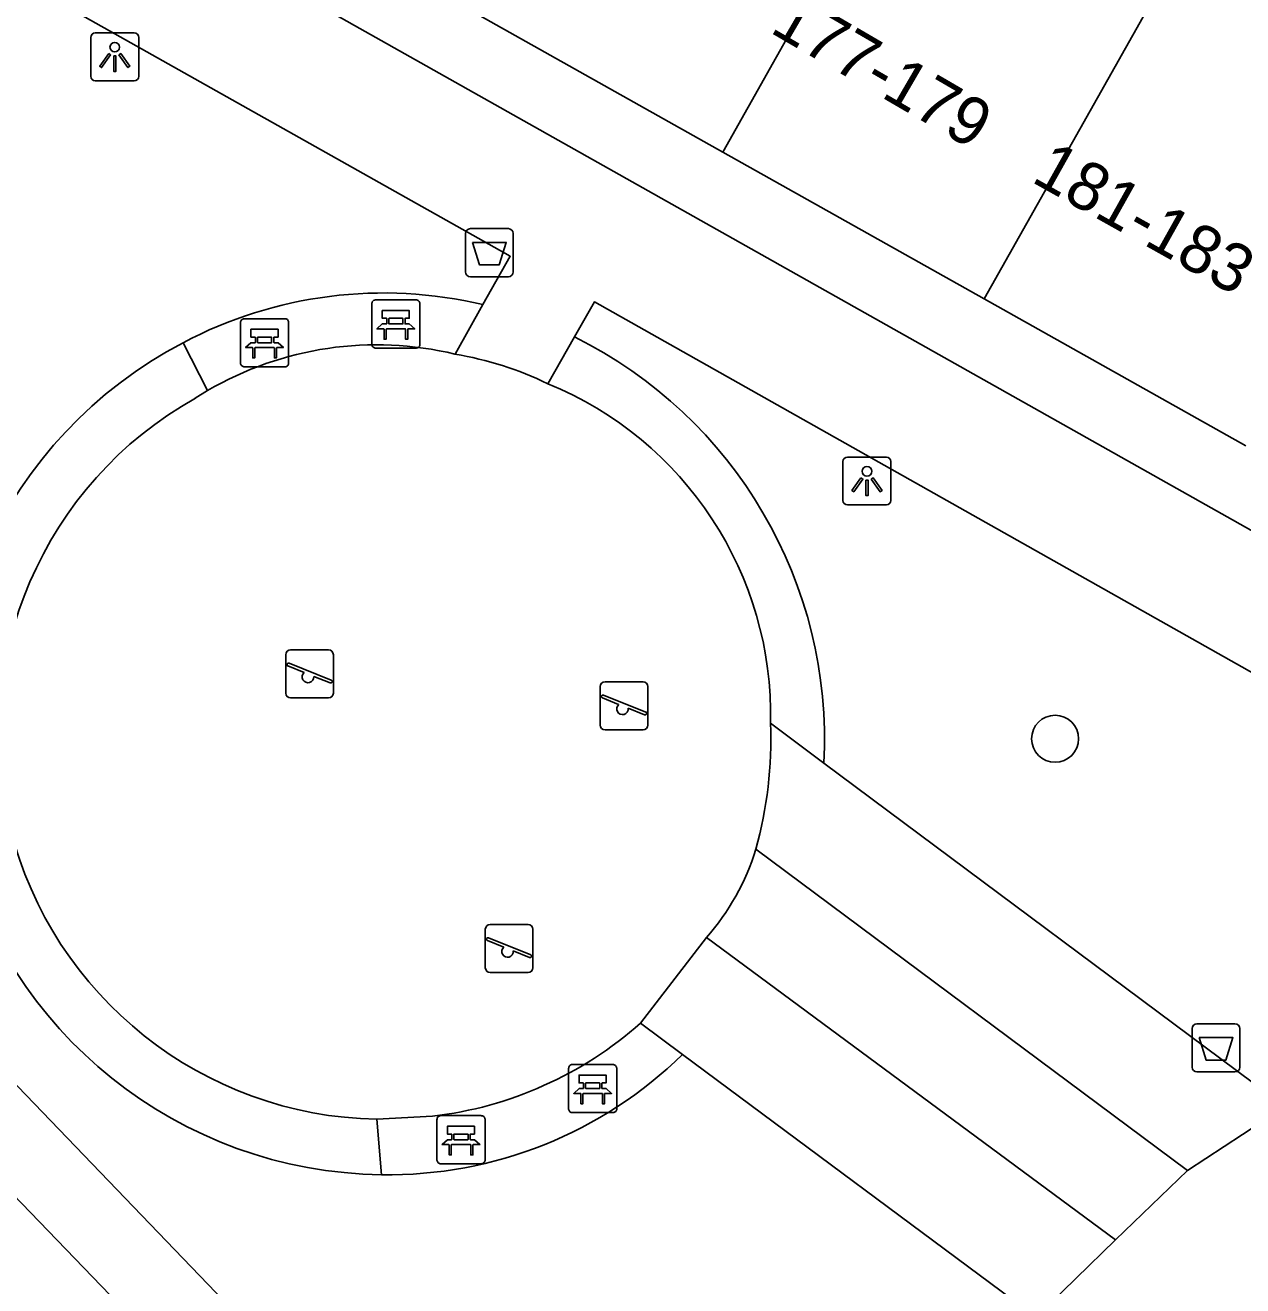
# Model space of a CAD drawing. Extents: x 159280 to 160375, y 384531 to 385872.
# Drawn here: x 159682.94 to 159708.26, y 384897.02 to 384923.23 of the extents above; entities that cross this region are included whole.
import ezdxf

# ---------------------------------------------------------------- set-up
doc = ezdxf.new("R2010")
doc.units = 0
for name, color, linetype in [('IMGEO_Afvalbak', 7, 'Continuous'), ('IMGEO_Bank', 7, 'Continuous'), ('IMGEO_Boom', 7, 'Continuous'), ('IMGEO_Groenvoorziening', 7, 'Continuous'), ('IMGEO_Haag', 7, 'Continuous'), ('IMGEO_Lichtpunt', 7, 'Continuous'), ('IMGEO_Pand', 7, 'Continuous'), ('IMGEO_Pand_nummerreeks', 7, 'Continuous'), ('IMGEO_Speelvoorziening', 7, 'Continuous'), ('IMGEO_Voetpad_open', 7, 'Continuous')]:
    doc.layers.add(name, color=color, linetype=linetype)

msp = doc.modelspace()

# ---------------------------------------------------------------- linework, layer by layer
at = {"layer": 'IMGEO_Afvalbak'}
for p, q in [((159692.098, 384918.1), (159692.098, 384918.9)), ((159692.098, 384918.9), (159692.098, 384918.1)), ((159692.198, 384919), (159692.988, 384919)), ((159692.988, 384919), (159692.198, 384919)), ((159693.088, 384918.9), (159693.088, 384918.1)), ((159693.088, 384918.1), (159693.088, 384918.9)), ((159692.988, 384918), (159692.198, 384918)), ((159692.198, 384918), (159692.988, 384918)), ((159707.207, 384901.565), (159707.207, 384902.365)), ((159707.207, 384902.365), (159707.207, 384901.565)), ((159707.307, 384902.465), (159708.097, 384902.465)), ((159708.097, 384902.465), (159707.307, 384902.465)), ((159708.197, 384902.365), (159708.197, 384901.565)), ((159708.197, 384901.565), (159708.197, 384902.365)), ((159708.097, 384901.465), (159707.307, 384901.465)), ((159707.307, 384901.465), (159708.097, 384901.465))]:
    msp.add_line(p, q, dxfattribs=at)
for points in [[(159692.241, 384918.714), (159692.945, 384918.714), (159692.796, 384918.244), (159692.39, 384918.244), (159692.241, 384918.714)], [(159707.35, 384902.179), (159708.054, 384902.179), (159707.905, 384901.709), (159707.499, 384901.709), (159707.35, 384902.179)]]:
    msp.add_lwpolyline(points, dxfattribs=at)
for centre, start, end in [((159692.198, 384918.9), 90, 180), ((159692.198, 384918.9), 90, 180), ((159692.988, 384918.9), 0, 90), ((159692.988, 384918.9), 360, 90), ((159692.198, 384918.1), 180, 270), ((159692.198, 384918.1), 180, 270), ((159692.988, 384918.1), 270, 0), ((159692.988, 384918.1), 270, 0), ((159707.307, 384902.365), 90, 180), ((159707.307, 384902.365), 90, 180), ((159708.097, 384902.365), 0, 90), ((159708.097, 384902.365), 360, 90), ((159707.307, 384901.565), 180, 270), ((159707.307, 384901.565), 180, 270), ((159708.097, 384901.565), 270, 0), ((159708.097, 384901.565), 270, 0)]:
    msp.add_arc(centre, 0.1, start, end, dxfattribs=at)
at = {"layer": 'IMGEO_Bank'}
for p, q in [((159690.223, 384917.517), (159691.064, 384917.517)), ((159691.064, 384917.517), (159690.223, 384917.517)), ((159690.148, 384916.592), (159690.148, 384917.433)), ((159690.148, 384917.433), (159690.148, 384916.592)), ((159691.148, 384917.442), (159691.148, 384916.601)), ((159691.148, 384916.601), (159691.148, 384917.442)), ((159687.418, 384916.202), (159687.418, 384917.043)), ((159687.418, 384917.043), (159687.418, 384916.202)), ((159687.493, 384917.127), (159688.334, 384917.127)), ((159688.334, 384917.127), (159687.493, 384917.127)), ((159688.418, 384917.052), (159688.418, 384916.211)), ((159688.418, 384916.211), (159688.418, 384917.052)), ((159690.457, 384917.023), (159690.457, 384917.129)), ((159690.501, 384917.129), (159690.501, 384917.023)), ((159690.789, 384917.135), (159690.507, 384917.135)), ((159690.507, 384917.017), (159690.789, 384917.017)), ((159690.795, 384917.023), (159690.795, 384917.129)), ((159690.839, 384917.129), (159690.839, 384917.023)), ((159687.727, 384916.633), (159687.727, 384916.739)), ((159687.771, 384916.739), (159687.771, 384916.633)), ((159688.059, 384916.745), (159687.777, 384916.745)), ((159688.065, 384916.633), (159688.065, 384916.739)), ((159688.109, 384916.739), (159688.109, 384916.633)), ((159690.845, 384916.915), (159690.452, 384916.915)), ((159688.115, 384916.525), (159687.722, 384916.525)), ((159687.777, 384916.627), (159688.059, 384916.627)), ((159691.073, 384916.517), (159690.232, 384916.517)), ((159690.232, 384916.517), (159691.073, 384916.517)), ((159688.343, 384916.127), (159687.502, 384916.127)), ((159687.502, 384916.127), (159688.343, 384916.127)), ((159694.241, 384900.694), (159694.241, 384901.535)), ((159694.241, 384901.535), (159694.241, 384900.694)), ((159694.316, 384901.619), (159695.157, 384901.619)), ((159695.157, 384901.619), (159694.316, 384901.619)), ((159695.241, 384901.544), (159695.241, 384900.703)), ((159695.241, 384900.703), (159695.241, 384901.544)), ((159694.882, 384901.237), (159694.6, 384901.237)), ((159694.938, 384901.017), (159694.545, 384901.017)), ((159694.55, 384901.125), (159694.55, 384901.231)), ((159694.594, 384901.231), (159694.594, 384901.125)), ((159694.6, 384901.119), (159694.882, 384901.119)), ((159694.888, 384901.125), (159694.888, 384901.231)), ((159694.932, 384901.231), (159694.932, 384901.125)), ((159691.503, 384899.631), (159691.503, 384900.472)), ((159691.503, 384900.472), (159691.503, 384899.631)), ((159691.578, 384900.556), (159692.419, 384900.556)), ((159692.419, 384900.556), (159691.578, 384900.556)), ((159692.503, 384900.481), (159692.503, 384899.64)), ((159692.503, 384899.64), (159692.503, 384900.481)), ((159695.166, 384900.619), (159694.325, 384900.619)), ((159694.325, 384900.619), (159695.166, 384900.619)), ((159692.2, 384899.954), (159691.807, 384899.954)), ((159691.812, 384900.062), (159691.812, 384900.168)), ((159691.856, 384900.168), (159691.856, 384900.062)), ((159692.144, 384900.174), (159691.862, 384900.174)), ((159691.862, 384900.056), (159692.144, 384900.056)), ((159692.15, 384900.062), (159692.15, 384900.168)), ((159692.194, 384900.168), (159692.194, 384900.062)), ((159692.428, 384899.556), (159691.587, 384899.556)), ((159691.587, 384899.556), (159692.428, 384899.556))]:
    msp.add_line(p, q, dxfattribs=at)
for points in [[(159690.451, 384917.135), (159690.365, 384917.135), (159690.365, 384917.296), (159690.928, 384917.296), (159690.928, 384917.135), (159690.845, 384917.135)], [(159690.395, 384916.915), (159690.253, 384916.915), (159690.365, 384917.017), (159690.451, 384917.017)], [(159690.845, 384917.017), (159690.928, 384917.017), (159691.04, 384916.915), (159690.901, 384916.915)], [(159687.721, 384916.745), (159687.635, 384916.745), (159687.635, 384916.906), (159688.198, 384916.906), (159688.198, 384916.745), (159688.115, 384916.745)], [(159690.445, 384916.908), (159690.445, 384916.701), (159690.402, 384916.701), (159690.402, 384916.908)], [(159690.895, 384916.908), (159690.895, 384916.701), (159690.851, 384916.701), (159690.851, 384916.908)], [(159687.665, 384916.525), (159687.523, 384916.525), (159687.635, 384916.627), (159687.721, 384916.627)], [(159687.715, 384916.518), (159687.715, 384916.311), (159687.672, 384916.311), (159687.672, 384916.518)], [(159688.115, 384916.627), (159688.198, 384916.627), (159688.31, 384916.525), (159688.171, 384916.525)], [(159688.165, 384916.518), (159688.165, 384916.311), (159688.121, 384916.311), (159688.121, 384916.518)], [(159694.544, 384901.237), (159694.458, 384901.237), (159694.458, 384901.398), (159695.021, 384901.398), (159695.021, 384901.237), (159694.938, 384901.237)], [(159694.488, 384901.017), (159694.346, 384901.017), (159694.458, 384901.119), (159694.544, 384901.119)], [(159694.538, 384901.01), (159694.538, 384900.803), (159694.495, 384900.803), (159694.495, 384901.01)], [(159694.938, 384901.119), (159695.021, 384901.119), (159695.133, 384901.017), (159694.994, 384901.017)], [(159694.988, 384901.01), (159694.988, 384900.803), (159694.944, 384900.803), (159694.944, 384901.01)], [(159691.806, 384900.174), (159691.72, 384900.174), (159691.72, 384900.335), (159692.283, 384900.335), (159692.283, 384900.174), (159692.2, 384900.174)], [(159691.75, 384899.954), (159691.608, 384899.954), (159691.72, 384900.056), (159691.806, 384900.056)], [(159691.8, 384899.947), (159691.8, 384899.74), (159691.757, 384899.74), (159691.757, 384899.947)], [(159692.2, 384900.056), (159692.283, 384900.056), (159692.395, 384899.954), (159692.256, 384899.954)], [(159692.25, 384899.947), (159692.25, 384899.74), (159692.206, 384899.74), (159692.206, 384899.947)]]:
    msp.add_lwpolyline(points, dxfattribs=at)
for centre, radius, start, end in [((159690.226, 384917.439), 0.0779, 92.4484, 184.2845), ((159690.226, 384917.439), 0.0779, 92.4484, 184.2845), ((159691.07, 384917.439), 0.0779, 2.4484, 94.2845), ((159691.07, 384917.439), 0.0779, 2.4484, 94.2845), ((159687.496, 384917.049), 0.0779, 92.4484, 184.2845), ((159687.496, 384917.049), 0.0779, 92.4484, 184.2845), ((159688.34, 384917.049), 0.0779, 2.4484, 94.2845), ((159688.34, 384917.049), 0.0779, 2.4484, 94.2845), ((159690.45, 384917.128), 0.00671, 2.8957, 87.1043), ((159690.45, 384917.024), 0.00671, 272.8957, 357.1043), ((159690.507, 384917.128), 0.00671, 92.8957, 177.1043), ((159690.507, 384917.024), 0.00671, 182.8957, 267.1043), ((159690.789, 384917.128), 0.00671, 2.8957, 87.1043), ((159690.789, 384917.024), 0.00671, 272.8957, 357.1043), ((159690.846, 384917.128), 0.00671, 92.8957, 177.1043), ((159690.846, 384917.024), 0.00671, 182.8957, 267.1043), ((159687.72, 384916.738), 0.00671, 2.8957, 87.1043), ((159687.777, 384916.738), 0.00671, 92.8957, 177.1043), ((159688.059, 384916.738), 0.00671, 2.8957, 87.1043), ((159688.116, 384916.738), 0.00671, 92.8957, 177.1043), ((159690.395, 384916.908), 0.00671, 2.8957, 87.1043), ((159690.452, 384916.908), 0.00671, 92.8957, 177.1043), ((159690.844, 384916.908), 0.00671, 2.8957, 87.1043), ((159690.901, 384916.908), 0.00671, 92.8957, 177.1043), ((159687.665, 384916.518), 0.00671, 2.8957, 87.1043), ((159687.722, 384916.518), 0.00671, 92.8957, 177.1043), ((159687.72, 384916.634), 0.00671, 272.8957, 357.1043), ((159687.777, 384916.634), 0.00671, 182.8957, 267.1043), ((159688.059, 384916.634), 0.00671, 272.8957, 357.1043), ((159688.116, 384916.634), 0.00671, 182.8957, 267.1043), ((159688.114, 384916.518), 0.00671, 2.8957, 87.1043), ((159688.171, 384916.518), 0.00671, 92.8957, 177.1043), ((159690.226, 384916.595), 0.0779, 182.4484, 274.2845), ((159690.226, 384916.595), 0.0779, 182.4484, 274.2845), ((159691.07, 384916.595), 0.0779, 272.4484, 4.2845), ((159691.07, 384916.595), 0.0779, 272.4484, 4.2845), ((159687.496, 384916.205), 0.0779, 182.4484, 274.2845), ((159687.496, 384916.205), 0.0779, 182.4484, 274.2845), ((159688.34, 384916.205), 0.0779, 272.4484, 4.2845), ((159688.34, 384916.205), 0.0779, 272.4484, 4.2845), ((159694.319, 384901.541), 0.0779, 92.4484, 184.2845), ((159694.319, 384901.541), 0.0779, 92.4484, 184.2845), ((159695.163, 384901.541), 0.0779, 2.4484, 94.2845), ((159695.163, 384901.541), 0.0779, 2.4484, 94.2845), ((159694.543, 384901.23), 0.00671, 2.8957, 87.1043), ((159694.6, 384901.23), 0.00671, 92.8957, 177.1043), ((159694.882, 384901.23), 0.00671, 2.8957, 87.1043), ((159694.939, 384901.23), 0.00671, 92.8957, 177.1043), ((159694.488, 384901.01), 0.00671, 2.8957, 87.1043), ((159694.545, 384901.01), 0.00671, 92.8957, 177.1043), ((159694.543, 384901.126), 0.00671, 272.8957, 357.1043), ((159694.6, 384901.126), 0.00671, 182.8957, 267.1043), ((159694.882, 384901.126), 0.00671, 272.8957, 357.1043), ((159694.939, 384901.126), 0.00671, 182.8957, 267.1043), ((159694.937, 384901.01), 0.00671, 2.8957, 87.1043), ((159694.994, 384901.01), 0.00671, 92.8957, 177.1043), ((159691.581, 384900.478), 0.0779, 92.4484, 184.2845), ((159691.581, 384900.478), 0.0779, 92.4484, 184.2845), ((159692.425, 384900.478), 0.0779, 2.4484, 94.2845), ((159692.425, 384900.478), 0.0779, 2.4484, 94.2845), ((159694.319, 384900.697), 0.0779, 182.4484, 274.2845), ((159694.319, 384900.697), 0.0779, 182.4484, 274.2845), ((159695.163, 384900.697), 0.0779, 272.4484, 4.2845), ((159695.163, 384900.697), 0.0779, 272.4484, 4.2845), ((159691.75, 384899.947), 0.00671, 2.8957, 87.1043), ((159691.807, 384899.947), 0.00671, 92.8957, 177.1043), ((159691.805, 384900.167), 0.00671, 2.8957, 87.1043), ((159691.805, 384900.063), 0.00671, 272.8957, 357.1043), ((159691.862, 384900.167), 0.00671, 92.8957, 177.1043), ((159691.862, 384900.063), 0.00671, 182.8957, 267.1043), ((159692.144, 384900.167), 0.00671, 2.8957, 87.1043), ((159692.144, 384900.063), 0.00671, 272.8957, 357.1043), ((159692.201, 384900.167), 0.00671, 92.8957, 177.1043), ((159692.201, 384900.063), 0.00671, 182.8957, 267.1043), ((159692.199, 384899.947), 0.00671, 2.8957, 87.1043), ((159692.256, 384899.947), 0.00671, 92.8957, 177.1043), ((159691.581, 384899.634), 0.0779, 182.4484, 274.2845), ((159691.581, 384899.634), 0.0779, 182.4484, 274.2845), ((159692.425, 384899.634), 0.0779, 272.4484, 4.2845), ((159692.425, 384899.634), 0.0779, 272.4484, 4.2845)]:
    msp.add_arc(centre, radius, start, end, dxfattribs=at)
at = {"layer": 'IMGEO_Boom'}
msp.add_circle((159704.356, 384908.393), 0.489, dxfattribs=at)
at = {"layer": 'IMGEO_Groenvoorziening'}
msp.add_arc((159693.413, 384907.526), 4.931, 318.4779, 343.1327, dxfattribs=at)
at = {"layer": 'IMGEO_Haag'}
msp.add_lwpolyline([(159686.732, 384915.632), (159686.478, 384915.476)], dxfattribs=at)
for centre, radius, start, end in [((159690.218, 384908.371), 9.345, 357.0285, 63.6739), ((159690.469, 384908.498), 9.171, 117.5826, 269.2663), ((159690.991, 384908.878), 7.451, 358.7443, 67.7852), ((159690.397, 384908.49), 8.01, 119.2891, 268.9721)]:
    msp.add_arc(centre, radius, start, end, dxfattribs=at)
at = {"layer": 'IMGEO_Lichtpunt'}
for p, q in [((159685.206, 384923.07), (159684.398, 384923.07)), ((159685.206, 384923.07), (159684.398, 384923.07)), ((159684.304, 384922.975), (159684.304, 384922.168)), ((159684.304, 384922.975), (159684.304, 384922.168)), ((159685.3, 384922.168), (159685.3, 384922.975)), ((159685.3, 384922.168), (159685.3, 384922.975)), ((159684.398, 384922.074), (159685.206, 384922.074)), ((159684.398, 384922.074), (159685.206, 384922.074)), ((159699.946, 384914.156), (159699.946, 384913.349)), ((159699.946, 384914.156), (159699.946, 384913.349)), ((159700.848, 384914.251), (159700.04, 384914.251)), ((159700.848, 384914.251), (159700.04, 384914.251)), ((159700.942, 384913.349), (159700.942, 384914.156)), ((159700.942, 384913.349), (159700.942, 384914.156)), ((159700.04, 384913.255), (159700.848, 384913.255)), ((159700.04, 384913.255), (159700.848, 384913.255))]:
    msp.add_line(p, q, dxfattribs=at)
for points in [[(159684.678, 384922.639), (159684.717, 384922.611), (159684.529, 384922.349), (159684.491, 384922.376), (159684.678, 384922.639)], [(159684.78, 384922.591), (159684.827, 384922.591), (159684.827, 384922.269), (159684.78, 384922.269), (159684.78, 384922.591)], [(159684.89, 384922.611), (159684.928, 384922.638), (159685.115, 384922.376), (159685.076, 384922.348), (159684.89, 384922.611)], [(159700.32, 384913.82), (159700.359, 384913.792), (159700.171, 384913.53), (159700.133, 384913.557), (159700.32, 384913.82)], [(159700.532, 384913.792), (159700.57, 384913.819), (159700.757, 384913.557), (159700.718, 384913.529), (159700.532, 384913.792)], [(159700.422, 384913.772), (159700.469, 384913.772), (159700.469, 384913.45), (159700.422, 384913.45), (159700.422, 384913.772)]]:
    msp.add_lwpolyline(points, dxfattribs=at)
for centre in [(159684.803, 384922.773), (159700.445, 384913.954)]:
    msp.add_circle(centre, 0.0994, dxfattribs=at)
for centre, start, end in [((159684.398, 384922.975), 90, 180), ((159684.398, 384922.975), 90, 180), ((159685.206, 384922.975), 0, 90), ((159685.206, 384922.975), 0, 90), ((159684.398, 384922.168), 180, 270), ((159684.398, 384922.168), 180, 270), ((159685.206, 384922.168), 270, 0), ((159685.206, 384922.168), 270, 360), ((159700.04, 384914.156), 90, 180), ((159700.04, 384914.156), 90, 180), ((159700.848, 384914.156), 0, 90), ((159700.848, 384914.156), 0, 90), ((159700.04, 384913.349), 180, 270), ((159700.04, 384913.349), 180, 270), ((159700.848, 384913.349), 270, 0), ((159700.848, 384913.349), 270, 360)]:
    msp.add_arc(centre, 0.0946, start, end, dxfattribs=at)
at = {"layer": 'IMGEO_Pand'}
for points in [[(159697.445, 384920.592), (159702.378, 384929.35)], [(159702.884, 384917.538), (159707.813, 384926.289)], [(159697.445, 384920.592), (159692.007, 384923.646)], [(159702.884, 384917.538), (159697.445, 384920.592)], [(159708.322, 384914.484), (159702.884, 384917.538)]]:
    msp.add_lwpolyline(points, dxfattribs=at)
at = {"layer": 'IMGEO_Speelvoorziening'}
for p, q in [((159688.458, 384910.241), (159689.248, 384910.241)), ((159689.248, 384910.241), (159688.458, 384910.241)), ((159688.358, 384909.341), (159688.358, 384910.141)), ((159688.358, 384910.141), (159688.358, 384909.341)), ((159688.741, 384909.769), (159688.402, 384909.906)), ((159688.427, 384909.966), (159689.303, 384909.613)), ((159689.348, 384910.141), (159689.348, 384909.341)), ((159689.348, 384909.341), (159689.348, 384910.141)), ((159689.279, 384909.553), (159688.939, 384909.69)), ((159694.898, 384908.677), (159694.898, 384909.477)), ((159694.898, 384909.477), (159694.898, 384908.677)), ((159694.998, 384909.577), (159695.788, 384909.577)), ((159695.788, 384909.577), (159694.998, 384909.577)), ((159695.888, 384909.477), (159695.888, 384908.677)), ((159695.888, 384908.677), (159695.888, 384909.477)), ((159689.248, 384909.241), (159688.458, 384909.241)), ((159688.458, 384909.241), (159689.248, 384909.241)), ((159695.281, 384909.105), (159694.942, 384909.242)), ((159694.967, 384909.302), (159695.843, 384908.949)), ((159695.819, 384908.889), (159695.479, 384909.026)), ((159695.788, 384908.577), (159694.998, 384908.577)), ((159694.998, 384908.577), (159695.788, 384908.577)), ((159692.508, 384903.631), (159692.508, 384904.431)), ((159692.508, 384904.431), (159692.508, 384903.631)), ((159692.608, 384904.531), (159693.398, 384904.531)), ((159693.398, 384904.531), (159692.608, 384904.531)), ((159693.498, 384904.431), (159693.498, 384903.631)), ((159693.498, 384903.631), (159693.498, 384904.431)), ((159692.891, 384904.059), (159692.552, 384904.196)), ((159692.577, 384904.256), (159693.453, 384903.903)), ((159693.429, 384903.843), (159693.089, 384903.98)), ((159693.398, 384903.531), (159692.608, 384903.531)), ((159692.608, 384903.531), (159693.398, 384903.531))]:
    msp.add_line(p, q, dxfattribs=at)
for centre, radius, start, end in [((159688.458, 384910.141), 0.1, 90, 180), ((159688.458, 384910.141), 0.1, 90, 180), ((159689.248, 384910.141), 0.1, 0, 90), ((159689.248, 384910.141), 0.1, 360, 90), ((159688.415, 384909.936), 0.0327, 68.078, 248.078), ((159688.82, 384909.679), 0.12, 130.9928, 5.1632), ((159689.291, 384909.583), 0.0327, 248.078, 68.078), ((159694.998, 384909.477), 0.1, 90, 180), ((159694.998, 384909.477), 0.1, 90, 180), ((159695.788, 384909.477), 0.1, 0, 90), ((159695.788, 384909.477), 0.1, 360, 90), ((159688.458, 384909.341), 0.1, 180, 270), ((159688.458, 384909.341), 0.1, 180, 270), ((159689.248, 384909.341), 0.1, 270, 0), ((159689.248, 384909.341), 0.1, 270, 0), ((159694.955, 384909.272), 0.0327, 68.078, 248.078), ((159695.36, 384909.015), 0.12, 130.9928, 5.1632), ((159695.831, 384908.919), 0.0327, 248.078, 68.078), ((159694.998, 384908.677), 0.1, 180, 270), ((159694.998, 384908.677), 0.1, 180, 270), ((159695.788, 384908.677), 0.1, 270, 0), ((159695.788, 384908.677), 0.1, 270, 0), ((159692.608, 384904.431), 0.1, 90, 180), ((159692.608, 384904.431), 0.1, 90, 180), ((159693.398, 384904.431), 0.1, 0, 90), ((159693.398, 384904.431), 0.1, 360, 90), ((159692.565, 384904.226), 0.0327, 68.078, 248.078), ((159692.97, 384903.969), 0.12, 130.9928, 5.1632), ((159693.441, 384903.873), 0.0327, 248.078, 68.078), ((159692.608, 384903.631), 0.1, 180, 270), ((159692.608, 384903.631), 0.1, 180, 270), ((159693.398, 384903.631), 0.1, 270, 0), ((159693.398, 384903.631), 0.1, 270, 0)]:
    msp.add_arc(centre, radius, start, end, dxfattribs=at)
at = {"layer": 'IMGEO_Voetpad_open'}
for points in [[(159654.078, 384944.948), (159653.389, 384943.716), (159717.281, 384907.744)], [(159653.442, 384932.135), (159672.072, 384910.18), (159675.664, 384906.203), (159686.373, 384895.097)], [(159692.459, 384917.419), (159693.028, 384918.426), (159682.858, 384924.153)], [(159691.878, 384916.391), (159692.459, 384917.419)], [(159713.23, 384907.077), (159694.777, 384917.475), (159694.362, 384916.747)], [(159694.362, 384916.747), (159693.808, 384915.776)], [(159686.732, 384915.632), (159686.223, 384916.627)], [(159693.444, 384890.083), (159674.873, 384909.387)], [(159699.55, 384907.887), (159698.44, 384908.715)], [(159699.55, 384907.887), (159709.133, 384900.743)], [(159698.132, 384906.095), (159707.111, 384899.413)], [(159695.735, 384902.481), (159697.105, 384904.257)], [(159697.105, 384904.257), (159705.613, 384897.977)], [(159696.611, 384901.831), (159695.735, 384902.481)], [(159703.964, 384896.367), (159696.611, 384901.831)], [(159709.133, 384900.743), (159708.256, 384900.166), (159707.111, 384899.413)], [(159691.409, 384900.544), (159690.253, 384900.481)], [(159690.253, 384900.481), (159690.352, 384899.328)], [(159707.111, 384899.413), (159705.613, 384897.977)], [(159705.613, 384897.977), (159703.964, 384896.367)]]:
    msp.add_lwpolyline(points, dxfattribs=at)
for centre, radius, start, end in [((159690.392, 384908.749), 8.913, 76.5902, 117.886), ((159690.247, 384909.621), 6.963, 76.4577, 120.3228), ((159690.66, 384909.234), 7.26, 64.3062, 80.3446), ((159689.925, 384908.388), 8.521, 344.3907, 2.1998), ((159690.497, 384908.381), 7.89, 276.6401, 311.6015), ((159690.487, 384908.067), 8.74, 269.1137, 314.4797)]:
    msp.add_arc(centre, radius, start, end, dxfattribs=at)

# ---------------------------------------------------------------- texts
at = {"layer": 'IMGEO_Pand_nummerreeks'}
for s, rotation, p in [('177-179', 329.7994, (159698.4, 384923.095)), ('181-183', 330.7505, (159703.835, 384919.988))]:
    msp.add_text(s, height=1, rotation=rotation, dxfattribs=at).set_placement(p)

doc.saveas('drawing.dxf')
